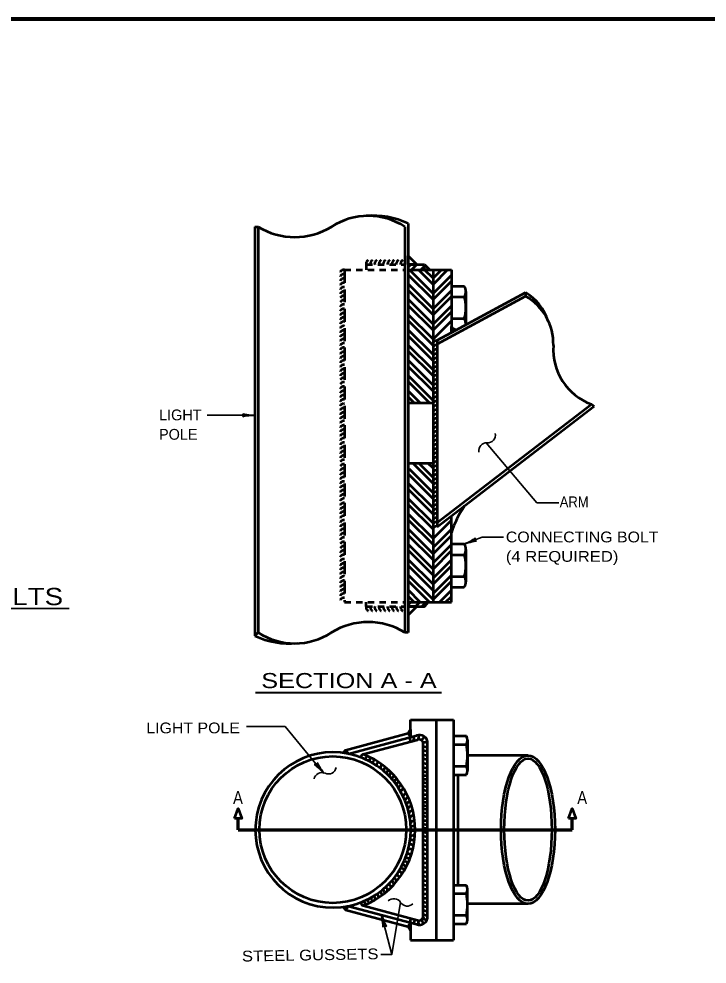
# Model space of a CAD drawing. Extents: x -23 to 690, y -228 to 443.
# Drawn here: x 356 to 515.3, y 218.8 to 437.8 of the extents above; entities that cross this region are included whole.
import ezdxf
from ezdxf.enums import TextEntityAlignment as Align

# ---------------------------------------------------------------- set-up
doc = ezdxf.new("R2010")
doc.units = 0
doc.linetypes.add('MEDIUM_DASHED', pattern=[4.5, 3, -1.5])
doc.linetypes.add('SHORT_DASHED', pattern=[2.7, 1.5, -1.2])
doc.layers.add('1', color=7, linetype='Continuous', lineweight=35)

msp = doc.modelspace()

# ---------------------------------------------------------------- linework, layer by layer
at = {"layer": '1', "lineweight": 53}
for p, q in [((410.626, 389.642), (410.626, 294.892)), ((410.626, 389.642), (411.376, 389.642)), ((411.376, 389.642), (411.376, 295.642)), ((445.376, 389.642), (445.376, 295.642)), ((446.126, 380.892), (449.876, 380.892)), ((446.126, 379.642), (446.126, 295.642)), ((446.126, 379.642), (449.876, 379.642)), ((446.741, 380.892), (446.148, 380.299)), ((451.876, 374.173), (446.407, 379.642)), ((448.156, 380.892), (446.906, 379.642)), ((451.876, 376.295), (448.529, 379.642)), ((449.876, 380.491), (449.027, 379.642)), ((449.876, 380.892), (451.126, 379.642)), ((449.876, 379.642), (451.109, 379.642)), ((451.876, 377.709), (449.943, 379.642)), ((451.126, 379.642), (456.126, 379.642)), ((451.876, 379.642), (451.876, 302.642)), ((455.223, 379.642), (451.876, 376.295)), ((453.809, 379.642), (451.876, 377.709)), ((451.876, 372.759), (446.126, 378.509)), ((456.133, 378.43), (451.876, 374.173)), ((456.134, 377.017), (451.876, 372.759)), ((451.876, 370.638), (446.126, 376.388)), ((451.876, 369.223), (446.126, 374.973)), ((456.134, 374.895), (451.876, 370.638)), ((456.126, 375.892), (459.126, 375.892)), ((459.496, 374.642), (459.496, 367.093)), ((451.876, 367.102), (446.126, 372.852)), ((456.134, 373.481), (451.876, 369.223)), ((452.884, 362.549), (473.303, 373.544)), ((456.126, 373.392), (459.126, 373.392)), ((473.295, 374.387), (473.303, 373.544)), ((451.876, 365.688), (446.126, 371.438)), ((456.134, 371.36), (451.876, 367.102)), ((451.876, 363.566), (446.126, 369.316)), ((456.134, 369.945), (451.876, 365.688)), ((456.126, 368.392), (459.126, 368.392)), ((456.126, 368.392), (456.126, 365.142)), ((451.876, 362.152), (446.126, 367.902)), ((451.876, 360.031), (446.126, 365.781)), ((456.134, 367.824), (451.876, 363.566)), ((456.126, 365.142), (456.126, 366.507)), ((457.386, 365.82), (456.126, 365.142)), ((451.876, 358.616), (446.126, 364.366)), ((451.876, 356.495), (446.126, 362.245)), ((452.876, 363.392), (452.876, 320.142)), ((451.876, 355.081), (446.126, 360.831)), ((451.876, 352.959), (446.126, 358.709)), ((451.876, 351.545), (446.126, 357.295)), ((451.876, 349.424), (446.126, 355.174)), ((451.118, 348.767), (446.126, 353.759)), ((448.997, 348.767), (446.126, 351.638)), ((447.583, 348.767), (446.126, 350.224)), ((451.876, 348.767), (446.126, 348.767)), ((451.876, 334.767), (446.126, 334.767)), ((451.877, 328.024), (446.408, 333.492)), ((451.877, 330.145), (447.255, 334.767)), ((451.877, 331.56), (448.669, 334.767)), ((451.876, 333.681), (450.791, 334.767)), ((451.877, 326.61), (446.127, 332.36)), ((451.877, 324.488), (446.127, 330.238)), ((451.877, 323.074), (446.127, 328.824)), ((451.877, 320.953), (446.127, 326.703)), ((451.877, 319.538), (446.127, 325.288)), ((451.877, 317.417), (446.127, 323.167)), ((456.126, 318.779), (456.126, 322.642)), ((451.877, 316.003), (446.127, 321.753)), ((451.876, 317.416), (456.134, 321.674)), ((451.877, 313.881), (446.127, 319.631)), ((451.877, 312.467), (446.127, 318.217)), ((451.876, 315.295), (456.134, 319.553)), ((451.876, 313.881), (456.134, 318.138)), ((451.877, 310.346), (446.127, 316.096)), ((451.876, 311.759), (456.134, 316.017)), ((456.126, 316.142), (459.126, 316.142)), ((451.877, 308.931), (446.127, 314.681)), ((451.876, 310.345), (456.134, 314.603)), ((456.126, 313.642), (459.126, 313.642)), ((459.496, 314.892), (459.496, 307.343)), ((451.877, 306.81), (446.127, 312.56)), ((451.877, 305.396), (446.127, 311.146)), ((451.876, 308.224), (456.134, 312.481)), ((451.876, 306.809), (456.134, 311.067)), ((451.877, 303.274), (446.127, 309.024)), ((451.876, 304.688), (456.134, 308.946)), ((451.119, 302.617), (446.127, 307.61)), ((451.877, 303.274), (456.134, 307.531)), ((456.126, 308.642), (459.126, 308.642)), ((448.998, 302.617), (446.127, 305.489)), ((453.365, 302.642), (456.134, 305.41)), ((456.126, 306.142), (459.126, 306.142)), ((447.583, 302.617), (446.127, 304.074)), ((446.133, 302.06), (446.716, 302.642)), ((447.854, 301.659), (448.837, 302.642)), ((449.268, 301.659), (449.876, 302.266)), ((449.876, 301.642), (450.724, 302.642)), ((454.78, 302.642), (456.134, 303.996)), ((446.126, 301.642), (449.876, 301.642)), ((410.626, 294.892), (411.376, 295.642)), ((446.126, 295.642), (445.376, 295.642)), ((446.626, 275.411), (456.626, 275.411)), ((452.626, 275.411), (452.626, 224.373)), ((456.626, 275.411), (456.626, 224.373)), ((431.626, 268.392), (446.115, 272.274)), ((432.301, 267.537), (448.058, 271.759)), ((446.115, 272.274), (446.626, 273.173)), ((456.626, 271.661), (459.626, 271.661)), ((435.706, 267.414), (448.316, 270.793)), ((449.626, 229.892), (449.626, 269.892)), ((450.626, 229.892), (450.626, 269.892)), ((456.626, 269.661), (459.626, 269.661)), ((459.876, 270.661), (459.876, 263.661)), ((431.626, 268.392), (431.108, 267.737)), ((431.626, 268.392), (432.301, 267.537)), ((473.876, 267.161), (459.876, 267.161)), ((456.626, 264.661), (459.626, 264.661)), ((456.626, 262.661), (459.626, 262.661)), ((457.626, 262.661), (457.626, 237.123)), ((456.626, 237.123), (459.626, 237.123)), ((456.626, 235.123), (459.626, 235.123)), ((459.876, 229.123), (459.876, 236.123)), ((431.626, 231.392), (432.301, 232.246)), ((432.301, 232.246), (448.058, 228.024)), ((435.706, 232.369), (448.316, 228.99)), ((473.876, 232.758), (459.876, 232.758)), ((431.626, 231.392), (431.108, 232.046)), ((431.626, 231.392), (446.598, 227.38)), ((456.626, 230.123), (459.626, 230.123)), ((446.115, 227.51), (446.626, 228.408)), ((446.626, 228.408), (446.626, 224.373)), ((446.626, 226.611), (446.626, 228.408)), ((456.626, 228.123), (459.626, 228.123)), ((446.626, 224.373), (456.626, 224.373))]:
    msp.add_line(p, q, dxfattribs=at)
at = {"layer": '1', "lineweight": 13}
msp.add_line((445.376, 381.892), (445.376, 380.892), dxfattribs=at)
at = {"layer": '1', "linetype": 'MEDIUM_DASHED', "lineweight": 53}
msp.add_line((431.376, 379.642), (431.376, 302.642), dxfattribs=at)
at = {"layer": '1', "linetype": 'SHORT_DASHED', "lineweight": 53}
for p, q in [((431.376, 379.642), (445.376, 379.642)), ((436.376, 380.892), (445.376, 380.892)), ((436.376, 380.892), (436.376, 379.642)), ((431.376, 302.642), (445.376, 302.642)), ((436.376, 301.642), (436.376, 302.642)), ((436.376, 301.642), (445.376, 301.642))]:
    msp.add_line(p, q, dxfattribs=at)
at = {"layer": '1'}
for p, q in [((410.626, 345.959), (399.569, 345.959)), ((272.629, 301.175), (367.649, 301.175)), ((442.36, 221.027), (439.799, 221.027))]:
    msp.add_line(p, q, dxfattribs=at)
at = {"layer": '1', "lineweight": 40}
msp.add_line((410.805, 281.73), (453.86, 281.73), dxfattribs=at)
at = {"layer": '1', "lineweight": 70}
for p, q in [((406.734, 249.892), (406.734, 252.543)), ((484.126, 249.892), (484.126, 252.543)), ((406.734, 249.892), (484.126, 249.892))]:
    msp.add_line(p, q, dxfattribs=at)
at = {"layer": '1', "lineweight": 158}
msp.add_lwpolyline([(684.026, 437.805), (24.276, 437.722), (24.36, -0.611)], dxfattribs=at)
at = {"layer": '1', "lineweight": 53}
for points in [[(446.126, 390.392), (446.126, 380.892), (446.126, 379.642)], [(456.126, 379.642), (456.126, 375.892), (456.126, 373.392), (456.126, 368.392)], [(452.876, 363.392), (456.126, 365.142), (473.295, 374.387)], [(452.876, 321.088), (488.562, 348.539), (489.218, 348.097)], [(452.876, 320.142), (459.141, 324.961), (489.218, 348.097)], [(456.126, 302.642), (456.126, 322.642), (459.141, 324.961)], [(446.126, 302.642), (450.724, 302.642), (456.126, 302.642)], [(446.626, 271.376), (446.626, 273.173), (446.626, 275.411)], [(431.108, 267.737), (431.626, 268.392), (432.301, 267.537)], [(431.108, 232.046), (431.626, 231.392), (432.301, 232.246)]]:
    msp.add_lwpolyline(points, dxfattribs=at)
for points in [[(446.126, 380.892), (446.126, 382.892), (448.126, 380.892)], [(449.876, 380.892), (451.126, 379.642), (449.876, 379.642)], [(449.876, 302.642), (450.724, 302.642), (449.876, 301.642)], [(446.126, 301.642), (446.126, 299.642), (448.126, 301.642)], [(446.115, 272.274), (446.626, 273.173), (446.626, 271.376)], [(405.879, 252.543), (406.734, 254.892), (407.589, 252.543)], [(483.271, 252.543), (484.126, 254.892), (484.981, 252.543)], [(446.115, 227.51), (446.626, 228.408), (446.626, 226.611)]]:
    msp.add_lwpolyline(points, close=True, dxfattribs=at)
at = {"layer": '1'}
for points in [[(464.152, 339.582), (475.94, 325.7), (480.976, 325.7)], [(459.126, 316.142), (463.29, 317.713), (468.202, 317.713)], [(426.552, 263.065), (417.634, 273.818), (408.716, 273.818)], [(444.352, 233.162), (442.36, 221.027), (439.977, 230.209)]]:
    msp.add_lwpolyline(points, dxfattribs=at)
at = {"layer": '1', "lineweight": 53}
msp.add_circle((428.677, 249.951), 17, dxfattribs=at)
for centre, radius, start, end in [((436.876, 376.588), 15.577, 56.92912, 123.07088), ((438.002, 373.339), 18.889, 64.52845, 94.9624), ((419.876, 403.543), 16.294, 238.55651, 301.44349), ((457.2, 374.642), 2.296, 327.01247, 32.98752), ((450.816, 370.892), 8.678, 343.25701, 16.74299), ((467.138, 364.06), 12.023, 17.99602, 59.19333), ((467.05, 362.494), 12.696, 358.41667, 60.49676), ((457.2, 367.142), 2.296, 355.26426, 32.98752), ((457.431, 367.401), 1.581, 214.41854, 268.39893), ((493.112, 361.151), 13.407, 175.75547, 250.16391), ((480.425, 310.754), 25.59, 146.27638, 161.72396), ((457.2, 314.892), 2.296, 327.01247, 32.98752), ((450.816, 311.142), 8.678, 343.25701, 16.74299), ((457.2, 307.392), 2.296, 327.01248, 32.98753), ((436.876, 281.74), 16.294, 58.55651, 121.44349), ((418.75, 311.945), 18.889, 244.52845, 274.9624), ((419.876, 308.695), 15.577, 236.92912, 303.07088), ((446.744, 271.06), 0.751, 320.93308, 42.22357), ((448.736, 269.993), 1.893, 356.94754, 111.01297), ((447.834, 271.484), 0.751, 308.93308, 30.22357), ((457.751, 270.661), 2.125, 331.92751, 28.07249), ((447.261, 270.975), 0.751, 147.77643, 229.06692), ((448.648, 269.873), 0.978, 1.08363, 109.83034), ((449.051, 271.557), 0.751, 275.93308, 357.22357), ((449.963, 270.964), 0.751, 243.93308, 325.22357), ((447.251, 267.161), 12.625, 348.57881, 11.42119), ((428.734, 249.895), 18, 78.57153, 78.56832), ((428.734, 249.895), 18, 78.56832, 82.41957), ((435.826, 266.807), 0.619, 101.14958, 189.27426), ((428.956, 249.892), 18.778, 291.06711, 68.93288), ((450.109, 269.918), 0.751, 228.93308, 310.22357), ((450.109, 268.971), 0.751, 228.93308, 310.22357), ((450.109, 267.989), 0.751, 228.93308, 310.22357), ((436.875, 266.413), 0.619, 101.14958, 189.27426), ((437.76, 265.987), 0.619, 101.14958, 189.27426), ((438.58, 265.528), 0.619, 101.14958, 189.27426), ((439.432, 265.003), 0.619, 101.14958, 189.27426), ((450.109, 266.024), 0.751, 228.93308, 310.22357), ((450.144, 267.042), 0.751, 228.93308, 310.22357), ((440.317, 264.38), 0.619, 101.14958, 189.27426), ((441.104, 263.724), 0.619, 101.14958, 189.27426), ((441.793, 263.101), 0.619, 101.14958, 189.27426), ((442.383, 262.51), 0.619, 101.14958, 189.27426), ((450.109, 265.042), 0.751, 228.93308, 310.22357), ((450.109, 264.095), 0.751, 228.93308, 310.22357), ((457.751, 263.661), 2.125, 331.92751, 28.07249), ((442.974, 261.704), 0.619, 94.14958, 182.27426), ((443.596, 261.081), 0.619, 94.14958, 203.72751), ((444.055, 260.393), 0.619, 94.14958, 182.27426), ((450.144, 263.218), 0.751, 228.93308, 310.22357), ((450.144, 261.569), 0.751, 228.93308, 310.22357), ((450.161, 262.376), 0.751, 228.93308, 310.22357), ((444.547, 259.638), 0.619, 94.14958, 182.27426), ((445.077, 258.736), 0.619, 82.14958, 170.27426), ((450.126, 260.727), 0.751, 228.93308, 310.22357), ((450.161, 259.797), 0.751, 228.93308, 310.22357), ((445.601, 257.621), 0.619, 82.14958, 170.27426), ((446.027, 256.702), 0.619, 82.14958, 170.27426), ((446.421, 255.751), 0.619, 82.14958, 170.27426), ((450.126, 257.885), 0.751, 228.93308, 310.22357), ((450.144, 258.832), 0.751, 228.93308, 310.22357), ((450.144, 257.043), 0.751, 228.93308, 310.22357), ((446.716, 254.734), 0.619, 82.14958, 170.27426), ((446.911, 253.647), 0.619, 69.14958, 157.27426), ((450.144, 256.236), 0.751, 228.93308, 310.22357), ((450.161, 255.447), 0.751, 228.93308, 310.22357), ((447.174, 252.564), 0.619, 69.14958, 157.27426), ((447.305, 251.318), 0.619, 69.14958, 157.27426), ((450.137, 252.813), 0.751, 228.93308, 310.22357), ((450.144, 254.587), 0.751, 228.93308, 310.22357), ((450.161, 253.763), 0.751, 228.93308, 310.22357), ((447.226, 250.128), 0.619, 48.14958, 136.27426), ((447.226, 249.078), 0.619, 48.14958, 136.27426), ((450.114, 251.911), 0.751, 228.93308, 310.22357), ((450.137, 251.033), 0.751, 228.93308, 310.22357), ((446.998, 246.913), 0.619, 31.14958, 119.27426), ((447.193, 247.963), 0.619, 48.14958, 136.27426), ((450.114, 250.059), 0.751, 228.93308, 310.22357), ((450.114, 249.133), 0.751, 228.93308, 310.22357), ((450.114, 248.184), 0.751, 228.93308, 310.22357), ((446.571, 244.827), 0.619, 31.14958, 119.27426), ((446.779, 245.893), 0.619, 31.14958, 119.27426), ((450.137, 247.21), 0.751, 228.93308, 310.22357), ((450.161, 246.142), 0.751, 228.93308, 310.22357), ((445.864, 242.764), 0.619, 23.14958, 111.27426), ((446.16, 243.711), 0.619, 23.14958, 111.27426), ((450.114, 245.097), 0.751, 228.93308, 310.22357), ((450.161, 244.053), 0.751, 228.93308, 310.22357), ((444.616, 240.339), 0.619, 15.14958, 103.27426), ((444.971, 241.139), 0.619, 15.14958, 103.27426), ((445.45, 241.935), 0.619, 23.14958, 111.27426), ((450.114, 241.964), 0.751, 228.93308, 310.22357), ((450.161, 242.985), 0.751, 228.93308, 310.22357), ((443.521, 238.711), 0.619, 15.14958, 103.27426), ((444.083, 239.569), 0.619, 15.14958, 103.27426), ((450.161, 240.895), 0.751, 228.93308, 310.22357), ((450.161, 239.875), 0.751, 228.93308, 310.22357), ((440.733, 235.973), 0.619, 352.14958, 80.27426), ((441.547, 236.562), 0.619, 3.14958, 91.27426), ((442.198, 237.361), 0.619, 3.14958, 91.27426), ((442.82, 238.013), 0.619, 3.14958, 91.27426), ((450.131, 237.86), 0.751, 228.93308, 310.22357), ((450.192, 238.867), 0.751, 228.93308, 310.22357), ((457.751, 236.123), 2.125, 331.92751, 28.07249), ((437.891, 233.93), 0.619, 352.14958, 80.27426), ((438.69, 234.374), 0.619, 352.14958, 80.27426), ((439.43, 234.848), 0.619, 352.14958, 80.27426), ((440.081, 235.351), 0.619, 352.14958, 80.27426), ((450.1, 236.883), 0.751, 228.93308, 310.22357), ((450.161, 235.815), 0.751, 228.93308, 310.22357), ((447.251, 232.623), 12.625, 348.57881, 11.42119), ((428.734, 249.889), 18, 277.58043, 281.43168), ((435.826, 232.977), 0.619, 168.16306, 258.85042), ((435.553, 232.716), 0.619, 352.14958, 80.27426), ((436.382, 233.042), 0.619, 352.14958, 80.27426), ((437.151, 233.515), 0.619, 352.14958, 80.27426), ((450.161, 234.808), 0.751, 228.93308, 310.22357), ((450.192, 233.831), 0.751, 228.93308, 310.22357), ((450.222, 232.885), 0.751, 228.93308, 310.22357), ((450.161, 231.908), 0.751, 228.93308, 310.22357), ((450.271, 230.907), 0.751, 218.93308, 300.22357), ((457.751, 229.123), 2.125, 331.92751, 28.07249), ((447.305, 228.728), 0.751, 123.93308, 205.22357), ((448.22, 228.499), 0.751, 123.93308, 205.22357), ((448.736, 229.791), 1.893, 248.98703, 3.05246), ((448.648, 229.91), 0.978, 250.16966, 358.91637), ((449.157, 228.517), 0.751, 145.93308, 227.22357), ((450.062, 228.961), 0.751, 166.93308, 248.22357), ((450.362, 229.798), 0.751, 191.93308, 273.22357)]:
    msp.add_arc(centre, radius, start, end, dxfattribs=at)
at = {"layer": '1', "linetype": 'SHORT_DASHED', "lineweight": 53}
for centre, start, end in [((437.312, 381.049), 117.33592, 189.53397), ((438.312, 381.049), 117.33592, 189.53397), ((439.312, 381.049), 117.33592, 189.53397), ((440.312, 381.049), 117.33592, 189.53397), ((441.312, 381.049), 117.33592, 189.53397), ((442.312, 381.049), 117.33592, 189.53397), ((443.312, 381.049), 117.33592, 189.53397), ((444.312, 381.049), 117.33592, 189.53397), ((445.312, 381.049), 117.33592, 189.53397), ((431.219, 378.706), 80.46603, 152.66408), ((431.219, 378.706), 80.46603, 152.66408), ((431.219, 377.706), 80.46603, 152.66408), ((431.219, 376.706), 80.46603, 152.66408), ((431.219, 375.706), 80.46603, 152.66408), ((431.219, 374.706), 80.46603, 152.66408), ((431.219, 373.706), 80.46603, 152.66408), ((431.219, 372.706), 80.46603, 152.66408), ((431.219, 371.706), 80.46603, 152.66408), ((431.219, 370.706), 80.46603, 152.66408), ((431.219, 369.706), 80.46603, 152.66408), ((431.219, 368.706), 80.46603, 152.66408), ((431.219, 367.706), 80.46603, 152.66408), ((431.219, 366.706), 80.46603, 152.66408), ((431.219, 365.706), 80.46603, 152.66408), ((431.219, 364.706), 80.46603, 152.66408), ((431.219, 363.706), 80.46603, 152.66408), ((431.219, 362.706), 80.46603, 152.66408), ((431.219, 361.706), 80.46603, 152.66408), ((431.219, 360.706), 80.46603, 152.66408), ((452.719, 362.303), 80.46603, 152.66408), ((452.719, 361.303), 80.46603, 152.66408), ((431.219, 359.706), 80.46603, 152.66408), ((431.219, 358.706), 80.46603, 152.66408), ((452.719, 360.303), 80.46603, 152.66408), ((452.719, 359.303), 80.46603, 152.66408), ((452.719, 358.303), 80.46603, 152.66408), ((431.219, 357.706), 80.46603, 152.66408), ((431.219, 356.706), 80.46603, 152.66408), ((452.719, 357.303), 80.46603, 152.66408), ((452.719, 356.303), 80.46603, 152.66408), ((431.219, 355.706), 80.46603, 152.66408), ((431.219, 354.706), 80.46603, 152.66408), ((452.719, 355.303), 80.46603, 152.66408), ((452.719, 354.303), 80.46603, 152.66408), ((431.219, 353.706), 80.46603, 152.66408), ((431.219, 352.706), 80.46603, 152.66408), ((431.219, 351.706), 80.46603, 152.66408), ((452.719, 353.303), 80.46603, 152.66408), ((452.719, 352.303), 80.46603, 152.66408), ((431.219, 350.706), 80.46603, 152.66408), ((431.219, 349.706), 80.46603, 152.66408), ((452.719, 351.303), 80.46603, 152.66408), ((452.719, 350.303), 80.46603, 152.66408), ((431.219, 348.706), 80.46603, 152.66408), ((431.219, 347.706), 80.46603, 152.66408), ((452.719, 349.303), 80.46603, 152.66408), ((452.719, 348.303), 80.46603, 152.66408), ((452.719, 347.303), 80.46603, 152.66408), ((431.219, 346.706), 80.46603, 152.66408), ((431.219, 345.706), 80.46603, 152.66408), ((452.719, 346.303), 80.46603, 152.66408), ((452.719, 345.303), 80.46603, 152.66408), ((431.219, 344.706), 80.46603, 152.66408), ((431.219, 343.706), 80.46603, 152.66408), ((452.719, 344.303), 80.46603, 152.66408), ((452.719, 343.303), 80.46603, 152.66408), ((431.219, 342.706), 80.46603, 152.66408), ((431.219, 341.706), 80.46603, 152.66408), ((431.219, 340.706), 80.46603, 152.66408), ((452.719, 342.303), 80.46603, 152.66408), ((452.719, 341.303), 80.46603, 152.66408), ((431.219, 339.706), 80.46603, 152.66408), ((431.219, 338.706), 80.46603, 152.66408), ((452.719, 340.303), 80.46603, 152.66408), ((452.719, 339.303), 80.46603, 152.66408), ((431.219, 337.706), 80.46603, 152.66408), ((431.219, 336.706), 80.46603, 152.66408), ((452.719, 338.303), 80.46603, 152.66408), ((452.719, 337.303), 80.46603, 152.66408), ((431.219, 335.706), 80.46603, 152.66408), ((431.219, 334.706), 80.46603, 152.66408), ((452.719, 336.303), 80.46603, 152.66408), ((452.719, 335.303), 80.46603, 152.66408), ((452.719, 334.303), 80.46603, 152.66408), ((431.219, 333.706), 80.46603, 152.66408), ((431.219, 332.706), 80.46603, 152.66408), ((452.719, 333.303), 80.46603, 152.66408), ((452.719, 332.303), 80.46603, 152.66408), ((431.219, 331.706), 80.46603, 152.66408), ((431.219, 330.706), 80.46603, 152.66408), ((452.719, 331.303), 80.46603, 152.66408), ((452.719, 330.303), 80.46603, 152.66408), ((431.219, 329.706), 80.46603, 152.66408), ((431.219, 328.706), 80.46603, 152.66408), ((431.219, 327.706), 80.46603, 152.66408), ((452.719, 329.303), 80.46603, 152.66408), ((452.719, 328.303), 80.46603, 152.66408), ((431.219, 326.706), 80.46603, 152.66408), ((431.219, 325.706), 80.46603, 152.66408), ((452.719, 327.303), 80.46603, 152.66408), ((452.719, 326.303), 80.46603, 152.66408), ((431.219, 324.706), 80.46603, 152.66408), ((431.219, 323.706), 80.46603, 152.66408), ((452.719, 325.303), 80.46603, 152.66408), ((452.719, 324.303), 80.46603, 152.66408), ((452.719, 323.303), 80.46603, 152.66408), ((431.219, 322.706), 80.46603, 152.66408), ((431.219, 321.706), 80.46603, 152.66408), ((452.719, 322.303), 80.46603, 152.66408), ((452.719, 321.303), 80.46603, 152.66408), ((431.219, 320.706), 80.46603, 152.66408), ((431.219, 319.706), 80.46603, 152.66408), ((452.719, 320.303), 80.46603, 152.66408), ((452.719, 319.303), 80.46603, 152.66408), ((431.219, 318.706), 80.46603, 152.66408), ((431.219, 317.706), 80.46603, 152.66408), ((431.219, 316.706), 80.46603, 152.66408), ((431.219, 315.706), 80.46603, 152.66408), ((431.219, 314.706), 80.46603, 152.66408), ((431.219, 313.706), 80.46603, 152.66408), ((431.219, 312.706), 80.46603, 152.66408), ((431.219, 311.706), 80.46603, 152.66408), ((431.219, 310.706), 80.46603, 152.66408), ((431.219, 309.706), 80.46603, 152.66408), ((431.219, 308.706), 80.46603, 152.66408), ((431.219, 307.706), 80.46603, 152.66408), ((431.219, 306.706), 80.46603, 152.66408), ((431.219, 305.706), 80.46603, 152.66408), ((431.219, 304.706), 80.46603, 152.66408), ((431.219, 303.706), 80.46603, 152.66408), ((431.219, 302.706), 80.46603, 152.66408), ((437.312, 301.485), 170.46602, 242.66408), ((438.312, 301.485), 170.46602, 242.66408), ((439.312, 301.485), 170.46602, 242.66408), ((440.312, 301.485), 170.46602, 242.66408), ((441.312, 301.485), 170.46602, 242.66408), ((442.312, 301.485), 170.46602, 242.66408), ((443.312, 301.485), 170.46602, 242.66408), ((444.312, 301.485), 170.46602, 242.66408), ((445.312, 301.485), 170.46602, 242.66408)]:
    msp.add_arc(centre, 0.949, start, end, dxfattribs=at)
at = {"layer": '1'}
for centre, start, end in [((464.494, 341.415), 266.90049, 10.06203), ((464.296, 337.755), 86.90049, 190.06203), ((426.148, 261.342), 65.90049, 169.06203), ((427.645, 264.688), 245.90049, 349.06203), ((442.807, 232.134), 31.90049, 135.06203), ((445.919, 234.071), 211.90049, 315.06203)]:
    msp.add_arc(centre, 1.833, start, end, dxfattribs=at)
at = {"layer": '1', "lineweight": 40}
for centre, major_axis, ratio, start_param, end_param in [((409.505, 346.171), (-1.756, 0.176), 0.07063, 6.2823074, 8.5597026), ((409.535, 345.683), (1.786, 0.156), 0.122415, 0.8963533, 3.1415927), ((460.049, 316.786), (-1.616, -0.776), 0.122415, 0.8963533, 3.1415927), ((460.249, 316.339), (-1.705, -0.456), 0.07063, 3.1407148, 5.41811), ((425.642, 263.729), (1.26, -1.275), 0.122415, 0.8963533, 3.1415927), ((425.999, 264.063), (0.986, -1.464), 0.07063, 3.1407148, 5.41811), ((440.054, 229.071), (0.271, -1.744), 0.07063, 6.2823074, 8.5597026), ((440.519, 229.222), (-0.6, 1.689), 0.122415, 0.8963533, 3.1415927)]:
    msp.add_ellipse(centre, major_axis=major_axis, ratio=ratio, start_param=start_param, end_param=end_param, dxfattribs=at)
at = {"layer": '1', "lineweight": 53}
for major_axis, ratio in [((0, -17.202), 0.363338), ((0, -16.452), 0.334314)]:
    msp.add_ellipse((473.876, 249.959), major_axis=major_axis, ratio=ratio, dxfattribs=at)

# ---------------------------------------------------------------- texts
at = {"layer": '1'}
for s, p in [('LIGHT', (388.436, 344.798)), ('POLE', (388.436, 340.298))]:
    msp.add_text(s, height=2.5, dxfattribs=at).set_placement(p)
for s, height, width, p in [('ARM', 2.5, 0.9, (481.221, 324.667)), ('CONNECTING BOLT', 2.5, 1.1, (468.743, 316.515)), ('(4 REQUIRED)', 2.5, 1.15, (468.743, 312.015)), ('SECTION A - A', 3.5, 1.25, (412.098, 282.742)), ('LIGHT POLE', 2.5, 1.1, (385.498, 272.271)), ('A', 3, 0.85, (405.58, 255.892)), ('A', 3, 0.85, (485.28, 255.892))]:
    msp.add_text(s, height=height, dxfattribs=dict(at, width=width)).set_placement(p)
at = {"layer": '1', "width": 1.2}
msp.add_text('ARM ATTACHMENT - 2 BOLTS', height=4, dxfattribs=at).set_placement((320.218, 301.968), align=Align.CENTER)
at = {"layer": '1', "width": 1.15}
msp.add_text('STEEL GUSSETS', height=2.5, rotation=1, dxfattribs=at).set_placement((407.652, 219.382))

doc.saveas('drawing.dxf')
